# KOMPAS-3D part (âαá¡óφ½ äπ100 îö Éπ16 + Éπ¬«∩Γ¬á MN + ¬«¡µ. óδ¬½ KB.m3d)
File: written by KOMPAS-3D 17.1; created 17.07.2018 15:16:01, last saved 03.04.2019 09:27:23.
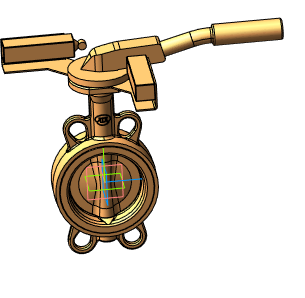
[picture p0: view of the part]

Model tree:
1. Операция без истории:2  (labels: Сталь 20  ГОСТ 1050-2013)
